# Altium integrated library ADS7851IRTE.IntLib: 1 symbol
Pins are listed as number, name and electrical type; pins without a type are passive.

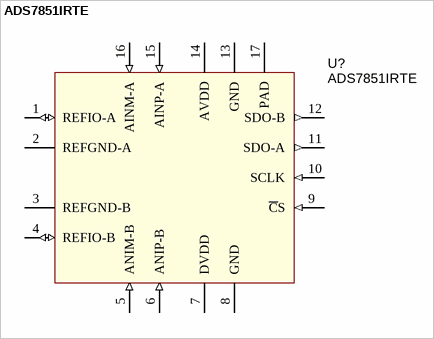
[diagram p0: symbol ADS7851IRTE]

## ADS7851IRTE
designator U?
Dual, 1.5-MSPS, 16 BIT Simultaneous Sampling ADC; Manufacturer: Texas Instruments
footprint RTE-16
pins: 1 REFIO-A (io), 2 REFGND-A, 3 REFGND-B, 4 REFIO-B (io), 5 ANIM-B (in), 6 ANIP-B (in), 7 DVDD (power), 8 GND (power), 9 ~{C}S (in), 10 SCLK (in), 11 SDO-A (out), 12 SDO-B (out), 13 GND, 14 AVDD (power), 15 AINP-A (in), 16 AINM-A (in), 17 PAD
